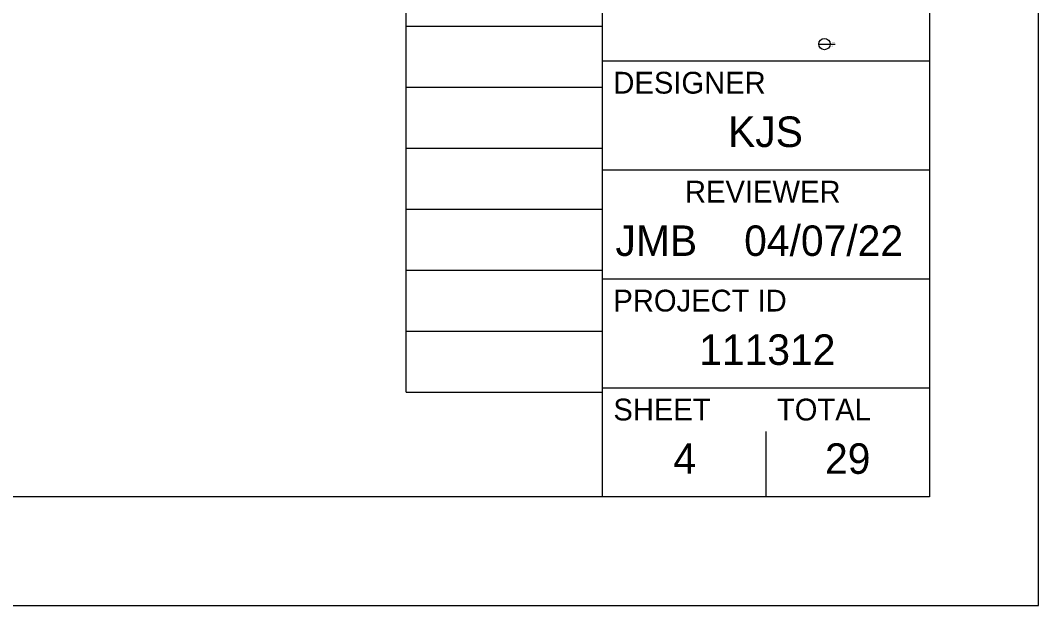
# Model space of a CAD drawing. Extents: x 0 to 34, y 0 to 22.
# Drawn here: x 29.331 to 34, y 0 to 2.686 of the extents above; entities that cross this region are included whole.
import ezdxf

# ---------------------------------------------------------------- set-up
doc = ezdxf.new("R2010")
doc.units = 0
for name, color, linetype in [('CS-ALGN-CNTR', 7, 'Continuous'), ('CS-ALGN-TEXT', 7, 'Continuous'), ('CS-ANNO', 7, 'Continuous'), ('CS-ANNO-MATC-MASK', 7, 'Continuous')]:
    doc.layers.add(name, color=color, linetype=linetype)

msp = doc.modelspace()

# ---------------------------------------------------------------- linework, layer by layer
at = {"layer": 'CS-ALGN-CNTR'}
msp.add_lwpolyline([(0, 0), (34, 0), (34, 22), (0, 22)], close=True, dxfattribs=at)
at = {"layer": 'CS-ALGN-TEXT'}
for p, q in [((32, 0.5), (32, 21.5)), ((32, 2.5), (33.5, 2.5)), ((32, 2), (33.5, 2)), ((32, 1.5), (33.5, 1.5)), ((32, 1), (33.5, 1))]:
    msp.add_line(p, q, dxfattribs=at)
msp.add_lwpolyline([(1.5, 21.5), (33.5, 21.5), (33.5, 0.5), (1.5, 0.5)], close=True, dxfattribs=at)
at = {"layer": 'CS-ANNO'}
for p, q in [((32.75, 0.5), (32.75, 0.8)), ((32.375, 0.675), (32.375, 0.675))]:
    msp.add_line(p, q, dxfattribs=at)
at = {"layer": 'CS-ANNO-MATC-MASK'}
for p, q in [((31.0995, 0.9796), (31.0995, 21.1396)), ((31.9995, 0.9796), (31.9995, 21.1396)), ((31.0995, 2.6596), (31.9995, 2.6596)), ((32.9919, 2.5774), (33.044, 2.5774)), ((33.0182, 2.5774), (33.0676, 2.5774)), ((31.0995, 2.3796), (31.9995, 2.3796)), ((31.0995, 2.0996), (31.9995, 2.0996)), ((31.0995, 1.8196), (31.9995, 1.8196)), ((31.0995, 1.5396), (31.9995, 1.5396)), ((31.0995, 1.2596), (31.9995, 1.2596)), ((31.0995, 0.9796), (31.9995, 0.9796))]:
    msp.add_line(p, q, dxfattribs=at)
msp.add_circle((33.0179, 2.5774), 0.026, dxfattribs=at)

# ---------------------------------------------------------------- texts
at = {"layer": 'CS-ANNO'}
for s, height, p in [('DESIGNER', 0.1, (32.05, 2.35)), ('KJS', 0.14, (32.5757, 2.105)), ('REVIEWER', 0.1, (32.3783, 1.85)), ('JMB', 0.14, (32.0596, 1.605)), ('04/07/22', 0.14, (32.6497, 1.605)), ('PROJECT ID', 0.1, (32.05, 1.35)), ('111312', 0.14, (32.4435, 1.105)), ('SHEET', 0.1, (32.05, 0.85)), ('TOTAL', 0.1, (32.8, 0.85)), ('29', 0.14, (33.0206, 0.605)), ('4', 0.14, (32.3254, 0.605))]:
    msp.add_text(s, height=height, dxfattribs=at).set_placement(p)
at = {"layer": 'CS-ANNO-MATC-MASK'}
for s, p in [('1', (33.0171, 2.584)), ('Drawing', (33.0507, 2.584)), ('1:2', (33.0507, 2.5676))]:
    msp.add_text(s, height=0.00328, dxfattribs=at).set_placement(p)

doc.saveas('drawing.dxf')
